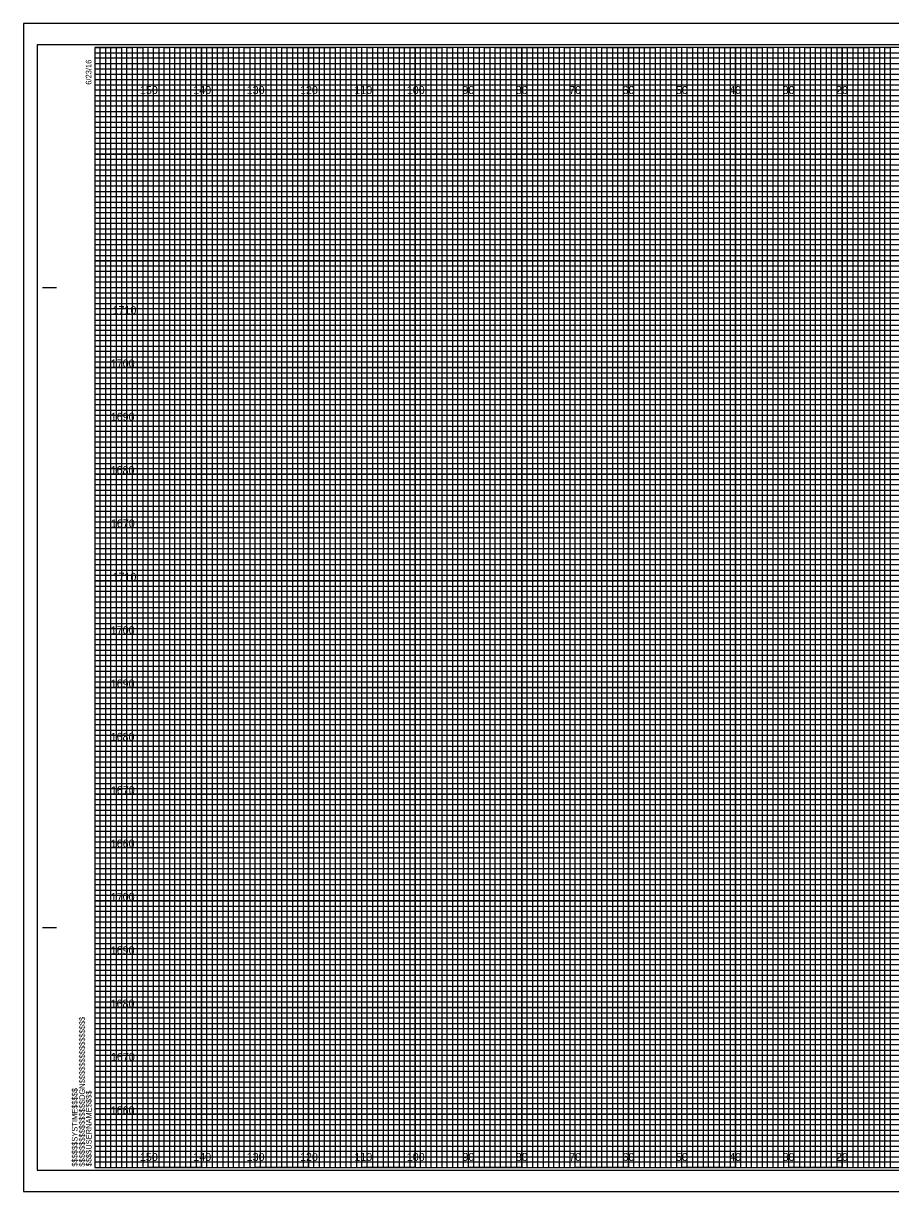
# Model space of a CAD drawing. Extents: x -13 to 323, y -5 to 2414.
# Drawn here: x -13.4 to 149.1, y 1975.5 to 2194.5 of the extents above; entities that cross this region are included whole.
import ezdxf

# ---------------------------------------------------------------- set-up
doc = ezdxf.new("R2010")
doc.units = 0
for name, color, linetype in [('Prop XS Elevation Labels', 7, 'Continuous'), ('Prop XS Offset Labels', 7, 'Continuous'), ('Sheet Cross Section CELL', 7, 'Continuous'), ('Sheet Cross Section Grid Major CELL', 7, 'Continuous'), ('Sheet Cross Section Grid Middle CELL', 7, 'Continuous'), ('Sheet Cross Section Grid Minor 1 CELL', 7, 'Continuous'), ('Sheet Cross Section Grid Minor 2 CELL', 7, 'Continuous'), ('Sheet Cutting Line CELL', 7, 'Continuous'), ('Sheet DOT Grid CELL', 7, 'Continuous'), ('Sheet Plot Border Inside CELL', 7, 'Continuous'), ('Sheet Plot Border Outside CELL', 7, 'Continuous')]:
    doc.layers.add(name, color=color, linetype=linetype)

msp = doc.modelspace()

# ---------------------------------------------------------------- linework, layer by layer
at = {"layer": 'Sheet Cross Section CELL'}
for p, q in [((-9.8, 2145), (-7.3, 2145)), ((-9.7, 2145), (-7.2, 2145)), ((-9.8, 2025), (-7.3, 2025)), ((-9.7, 2025), (-7.2, 2025)), ((0, 1980), (0, 1980)), ((0, 1980), (0, 1980)), ((0, 1980), (0, 1980)), ((0, 1980), (0, 1980)), ((0, 1980), (0, 1980)), ((0, 1980), (0, 1980)), ((0, 1980), (0, 1980))]:
    msp.add_line(p, q, dxfattribs=at)
msp.add_lwpolyline([(320, 2190), (0, 2190), (0, 1980), (320, 1980)], close=True, dxfattribs=at)
at = {"layer": 'Sheet Cross Section Grid Major CELL'}
for p, q in [((10, 2190), (0, 2190)), ((10, 1980), (10, 2190)), ((30, 2190), (20, 2190)), ((20, 2190), (20, 1980)), ((30, 1980), (30, 2190)), ((50, 2190), (40, 2190)), ((40, 2190), (40, 1980)), ((50, 1980), (50, 2190)), ((70, 2190), (60, 2190)), ((60, 2190), (60, 1980)), ((70, 1980), (70, 2190)), ((90, 2190), (80, 2190)), ((80, 2190), (80, 1980)), ((90, 1980), (90, 2190)), ((110, 2190), (100, 2190)), ((100, 2190), (100, 1980)), ((110, 1980), (110, 2190)), ((130, 2190), (120, 2190)), ((120, 2190), (120, 1980)), ((130, 1980), (130, 2190)), ((150, 2190), (140, 2190)), ((140, 2190), (140, 1980)), ((20, 1980), (10, 1980)), ((40, 1980), (30, 1980)), ((60, 1980), (50, 1980)), ((80, 1980), (70, 1980)), ((100, 1980), (90, 1980)), ((120, 1980), (110, 1980)), ((140, 1980), (130, 1980))]:
    msp.add_line(p, q, dxfattribs=at)
for points in [[(0, 2180), (320, 2180), (320, 2170), (0, 2170)], [(0, 2160), (320, 2160), (320, 2150), (0, 2150)], [(0, 2140), (320, 2140), (320, 2130), (0, 2130)], [(0, 2120), (320, 2120), (320, 2110), (0, 2110)], [(0, 2100), (320, 2100), (320, 2090), (0, 2090)], [(0, 2080), (320, 2080), (320, 2070), (0, 2070)], [(0, 2060), (320, 2060), (320, 2050), (0, 2050)], [(0, 2040), (320, 2040), (320, 2030), (0, 2030)], [(0, 2020), (320, 2020), (320, 2010), (0, 2010)], [(0, 2000), (320, 2000), (320, 1990), (0, 1990)]]:
    msp.add_lwpolyline(points, dxfattribs=at)
at = {"layer": 'Sheet Cross Section Grid Middle CELL'}
for points in [[(0, 2190), (5, 2190), (5, 1980), (15, 1980), (15, 2190), (25, 2190), (25, 1980), (35, 1980), (35, 2190), (45, 2190), (45, 1980), (55, 1980), (55, 2190), (65, 2190), (65, 1980), (75, 1980), (75, 2190), (85, 2190), (85, 1980), (95, 1980), (95, 2190), (105, 2190), (105, 1980), (115, 1980), (115, 2190), (125, 2190), (125, 1980), (135, 1980), (135, 2190), (145, 2190), (145, 1980), (155, 1980)], [(0, 2185), (275, 2185)], [(0, 2165), (320, 2165), (320, 2175), (0, 2175)], [(0, 2145), (320, 2145), (320, 2155), (0, 2155)], [(0, 2125), (320, 2125), (320, 2135), (0, 2135)], [(0, 2105), (320, 2105), (320, 2115), (0, 2115)], [(0, 2085), (320, 2085), (320, 2095), (0, 2095)], [(0, 2065), (320, 2065), (320, 2075), (0, 2075)], [(0, 2045), (320, 2045), (320, 2055), (0, 2055)], [(0, 2025), (320, 2025), (320, 2035), (0, 2035)], [(0, 2005), (320, 2005), (320, 2015), (0, 2015)], [(0, 1985), (320, 1985), (320, 1995), (0, 1995)]]:
    msp.add_lwpolyline(points, dxfattribs=at)
at = {"layer": 'Sheet Cross Section Grid Minor 1 CELL'}
for p, q in [((0, 2189), (260, 2189)), ((260, 2187.98), (0, 2187.98)), ((0, 2187.98), (0, 2187)), ((0, 2187), (260, 2187)), ((260, 2185.89), (0, 2185.89)), ((0, 2185.89), (0, 2184)), ((0, 2184), (320, 2184))]:
    msp.add_line(p, q, dxfattribs=at)
for points in [[(0, 2183), (270, 2183), (320, 2183), (320, 2182), (0, 2182)], [(0, 2181), (320, 2181), (320, 2179), (0, 2179)], [(0, 2178), (320, 2178), (320, 2177), (0, 2176.98)], [(0, 2176), (320, 2176), (320, 2174), (0, 2174)], [(0, 2173), (320, 2173), (320, 2172), (0, 2172)], [(0, 2171), (320, 2171), (320, 2169), (0, 2169)], [(0, 2168), (320, 2168), (320, 2167), (0, 2167)], [(0, 2166), (320, 2166), (320, 2164), (0, 2164)], [(0, 2163), (320, 2163), (320, 2162), (0, 2162)], [(0, 2161), (320, 2161), (320, 2159), (0, 2159)], [(0, 2158), (320, 2158), (320, 2157), (0, 2157)], [(0, 2156), (320, 2156), (320, 2153.95), (320, 2153), (320, 2152), (0, 2152)], [(0, 2154), (320, 2154), (320, 2153), (0, 2153)], [(0, 2151), (320, 2151), (320, 2149), (0, 2149.03)], [(0, 2149.03), (320, 2149), (320, 2148), (0, 2148)], [(0, 2147), (320, 2147), (320, 2146), (0, 2146)], [(0, 2144), (320, 2144), (320, 2143), (0, 2143)], [(0, 2142), (320, 2142), (320, 2141), (0, 2141)], [(-0.07, 2138.89), (320, 2138.89), (320, 2137.88), (-0.07, 2137.88)], [(0, 2137), (320, 2137), (320, 2136), (0, 2136)], [(0, 2134), (320, 2134), (320, 2133), (0, 2133)], [(0, 2132), (320, 2132), (320, 2131), (0, 2131)], [(0, 2129), (320, 2129), (320, 2128), (0, 2128)], [(0, 2127), (320, 2127), (320, 2126), (0, 2126)], [(0, 2124), (320, 2124), (320, 2123), (0, 2123)], [(0, 2122), (320, 2122), (320, 2121), (0, 2121)], [(0, 2119), (320, 2119), (319.99, 2117.98), (0, 2118)], [(0, 2117), (320, 2117), (320, 2116), (0, 2116)], [(0, 2114), (320, 2114), (320, 2113), (0, 2113)], [(0, 2112), (320, 2112), (320, 2111), (0, 2111)], [(0, 2109), (320, 2109), (320, 2108), (0, 2108)], [(0, 2107), (320, 2107), (320, 2106), (0, 2106)], [(0, 2104), (320, 2104), (320, 2103), (0, 2103)], [(0, 2102), (320, 2102), (320, 2101), (0, 2101)], [(0, 2099), (320, 2099), (320, 2098), (0, 2098)], [(0, 2096.99), (320.07, 2096.91), (320, 2096), (0, 2096)], [(0, 2094), (320, 2094), (320, 2093), (0, 2093)], [(0, 2092), (320, 2092), (320, 2091), (0, 2091)], [(0, 2089), (320, 2089), (320, 2088), (0, 2088)], [(0, 2087), (320, 2087), (320, 2086), (0, 2086)], [(0, 2084), (320, 2084), (320, 2083), (0, 2083)], [(0, 2082), (320, 2082), (320, 2081), (0, 2081)], [(0, 2079), (320, 2079), (320, 2078), (0, 2078)], [(0, 2077), (320, 2077), (320, 2076), (0, 2076)], [(0, 2074), (320, 2074), (320, 2073), (0, 2073)], [(0, 2072), (320, 2072), (320, 2071), (0, 2071)], [(0, 2069), (320, 2069), (320, 2068), (0, 2068)], [(0, 2067), (320, 2067), (320, 2066), (0, 2066)], [(0, 2064), (320, 2064), (320, 2063), (0, 2063)], [(0, 2062), (320, 2062), (320, 2061), (0, 2061)], [(0, 2059), (320, 2059), (319.99, 2057.98), (0, 2058)], [(0, 2057), (320, 2057), (320, 2056), (0, 2056)], [(0, 2054), (320, 2054), (320, 2053), (0, 2053)], [(0, 2052), (320, 2052), (320, 2051), (0, 2051)], [(0, 2049), (320, 2049), (320, 2048), (0, 2048)], [(0, 2047), (320, 2047), (320, 2046), (0, 2046)], [(0, 2044), (320, 2044), (320, 2043), (0, 2043)], [(0, 2042), (320, 2042), (320, 2041), (0, 2041)], [(0, 2039), (320, 2039), (320, 2038), (0, 2038)], [(0, 2036.99), (320.07, 2036.91), (320, 2036), (0, 2036)], [(0, 2034), (320, 2034), (320, 2033), (0, 2033)], [(0, 2032), (320, 2032), (320, 2031), (0, 2031)], [(0, 2029), (320, 2029), (320, 2028), (0, 2028)], [(0, 2027), (320, 2027), (320, 2026), (0, 2026)], [(0, 2024), (320, 2024), (320, 2023), (0, 2023)], [(0, 2022), (320, 2022), (320, 2021), (0, 2021)], [(0, 2019), (320, 2019), (320, 2018), (0, 2018)], [(0, 2017), (320, 2017), (320, 2016), (0, 2016)], [(0, 2014), (320, 2014), (320, 2013), (0, 2013)], [(0, 2012), (320, 2012), (320, 2011), (0, 2011)], [(0, 2009), (320, 2009), (320, 2008), (0, 2008)], [(0, 2007), (320, 2007), (320, 2006), (0, 2006)], [(0, 2004), (320, 2004), (320, 2003), (0, 2003)], [(0, 2002), (320, 2002), (320, 2001), (0, 2001)], [(0, 1999), (320, 1999), (320, 1998), (0, 1998)], [(0, 1997), (320, 1997), (320, 1996), (0, 1996)], [(0, 1994), (320, 1994), (320, 1993), (0, 1993)], [(0, 1992), (320, 1992), (320, 1991), (0, 1991)], [(0, 1989), (320, 1989), (320, 1988), (0, 1988)], [(0, 1987), (320, 1987), (320, 1986), (0, 1986)], [(0, 1984), (320, 1984), (320, 1983), (0, 1983)], [(0, 1982), (320, 1982), (320, 1981), (0, 1981)]]:
    msp.add_lwpolyline(points, dxfattribs=at)
at = {"layer": 'Sheet Cross Section Grid Minor 2 CELL'}
for points in [[(0, 1980), (1, 1980), (1, 2190), (2, 2190), (2, 1980)], [(2, 1980), (3, 1980), (3, 2190), (4, 2190), (4, 1980)], [(5, 1980), (6, 1980), (6, 2190), (7, 2190), (7, 1980)], [(7, 1980), (8, 1980), (8, 2190), (9, 2190), (9, 1980)], [(10, 1980), (11, 1980), (11, 2190), (12, 2190), (12, 1980)], [(12, 1980), (13, 1980), (13, 2190), (14, 2190), (14, 1980)], [(15, 1980), (16, 1980), (16, 2190), (17, 2190), (17, 1980)], [(17, 1980), (18, 1980), (18, 2190), (19, 2190), (19, 1980)], [(20, 1980), (21, 1980), (21, 2190), (22, 2190), (22, 1980)], [(22, 1980), (23, 1980), (23, 2190), (24, 2190), (24, 1980)], [(25, 1980), (26, 1980), (26, 2190), (27, 2190), (27, 1980)], [(27, 1980), (28, 1980), (28, 2190), (29, 2190), (29, 1980)], [(30, 1980), (31, 1980), (31, 2190), (32, 2190), (32, 1980)], [(32, 1980), (33, 1980), (33, 2190), (34, 2190), (34, 1980)], [(35, 1980), (36, 1980), (36, 2190), (37, 2190), (37, 1980)], [(37, 1980), (38, 1980), (38, 2190), (39, 2190), (39, 1980)], [(40, 1980), (41, 1980), (41, 2190), (42, 2190), (42, 1980)], [(42, 1980), (43, 1980), (43, 2190), (44, 2190), (44, 1980)], [(45, 1980), (46, 1980), (46, 2190), (47, 2190), (47, 1980)], [(47, 1980), (48, 1980), (48, 2190), (49, 2190), (49, 1980)], [(50, 1980), (51, 1980), (51, 2190), (52, 2190), (52, 1980)], [(52, 1980), (53, 1980), (53, 2190), (54, 2190), (54, 1980)], [(55, 1980), (56, 1980), (56, 2190), (57, 2190), (57, 1980)], [(57, 1980), (58, 1980), (58, 2190), (59, 2190), (59, 1980)], [(60, 1980), (61, 1980), (61, 2190), (62, 2190), (62, 1980)], [(62, 1980), (63, 1980), (63, 2190), (64, 2190), (64, 1980)], [(65, 1980), (66, 1980), (66, 2190), (67, 2190), (67, 1980)], [(67, 1980), (68, 1980), (68, 2190), (69, 2190), (69, 1980)], [(70, 1980), (71, 1980), (71, 2190), (72, 2190), (72, 1980)], [(72, 1980), (73, 1980), (73, 2190), (74, 2190), (74, 1980)], [(75, 1980), (76, 1980), (76, 2190), (77, 2190), (77, 1980)], [(77, 1980), (78, 1980), (78, 2190), (79, 2190), (79, 1980)], [(80, 1980), (81, 1980), (81, 2190), (82, 2190), (82, 1980)], [(82, 1980), (83, 1980), (83, 2190), (84, 2190), (84, 1980)], [(85, 1980), (86, 1980), (86, 2190), (87, 2190), (87, 1980)], [(87, 1980), (88, 1980), (88, 2190), (89, 2190), (89, 1980)], [(90, 1980), (91, 1980), (91, 2190), (92, 2190), (92, 1980)], [(92, 1980), (93, 1980), (93, 2190), (94, 2190), (94, 1980)], [(95, 1980), (96, 1980), (96, 2190), (97, 2190), (97, 1980)], [(97, 1980), (98, 1980), (98, 2190), (99, 2190), (99, 1980)], [(100, 1980), (101, 1980), (101, 2190), (102, 2190), (102, 1980)], [(102, 1980), (103, 1980), (103, 2190), (104, 2190), (104, 1980)], [(105, 1980), (106, 1980), (106, 2190), (107, 2190), (107, 1980)], [(107, 1980), (108, 1980), (108, 2190), (109, 2190), (109, 1980)], [(110, 1980), (111, 1980), (111, 2190), (112, 2190), (112, 1980)], [(112, 1980), (113, 1980), (113, 2190), (114, 2190), (114, 1980)], [(115, 1980), (116, 1980), (116, 2190), (117, 2190), (117, 1980)], [(117, 1980), (118, 1980), (118, 2190), (119, 2190), (119, 1980)], [(120, 1980), (121, 1980), (121, 2190), (122, 2190), (122, 1980)], [(122, 1980), (123, 1980), (123, 2190), (124, 2190), (124, 1980)], [(125, 1980), (126, 1980), (126, 2190), (127, 2190), (127, 1980)], [(127, 1980), (128, 1980), (128, 2190), (129, 2190), (129, 1980)], [(130, 1980), (131, 1980), (131, 2190), (132, 2190), (132, 1980)], [(132, 1980), (133, 1980), (133, 2190), (134, 2190), (134, 1980)], [(135, 1980), (136, 1980), (136, 2190), (137, 2190), (137, 1980)], [(137, 1980), (138, 1980), (138, 2190), (139, 2190), (139, 1980)], [(140, 1980), (141, 1980), (141, 2190), (142, 2190), (142, 1980)], [(142, 1980), (143, 1980), (143, 2190), (144, 2190), (144, 1980)], [(145, 1980), (146, 1980), (146, 2190), (147, 2190), (147, 1980)], [(147, 1980), (148, 1980), (148, 2190), (149, 2190), (149, 1980)]]:
    msp.add_lwpolyline(points, dxfattribs=at)
at = {"layer": 'Sheet Cutting Line CELL'}
for p, q in [((323.3, 2194.5), (-13.4, 2194.5)), ((-13.4, 2194.5), (-13.4, 1975.5)), ((-13.4, 1975.5), (323.3, 1975.5))]:
    msp.add_line(p, q, dxfattribs=at)
at = {"layer": 'Sheet DOT Grid CELL'}
for p, q in [((10, 1980), (10, 2190)), ((20, 1980), (20, 2190)), ((30, 1980), (30, 2190)), ((40, 1980), (40, 2190)), ((50, 1980), (50, 2190)), ((60, 1980), (60, 2190)), ((70, 1980), (70, 2190)), ((80, 1980), (80, 2190)), ((90, 1980), (90, 2190)), ((100, 1980), (100, 2190)), ((110, 1980), (110, 2190)), ((120, 1980), (120, 2190)), ((130, 1980), (130, 2190)), ((140, 1980), (140, 2190)), ((0, 2180), (320, 2180)), ((0, 2170), (320, 2170)), ((0, 2160), (320, 2160)), ((0, 2150), (320, 2150)), ((0, 2140), (320, 2140)), ((0, 2130), (320, 2130)), ((0, 2120), (320, 2120)), ((0, 2110), (320, 2110)), ((0, 2100), (320, 2100)), ((0, 2090), (320, 2090)), ((0, 2080), (320, 2080)), ((0, 2070), (320, 2070)), ((0, 2060), (320, 2060)), ((0, 2050), (320, 2050)), ((0, 2040), (320, 2040)), ((0, 2030), (320, 2030)), ((0, 2020), (320, 2020)), ((0, 2010), (320, 2010)), ((0, 2000), (320, 2000)), ((0, 1990), (320, 1990))]:
    msp.add_line(p, q, dxfattribs=at)
at = {"layer": 'Sheet Plot Border Inside CELL'}
msp.add_lwpolyline([(-10.8, 1979.5), (322.4, 1979.5), (322.4, 2190.5), (-10.8, 2190.5)], close=True, dxfattribs=at)
at = {"layer": 'Sheet Plot Border Outside CELL'}
msp.add_lwpolyline([(-13.4, 1975.5), (323.3, 1975.5), (323.3, 2194.5), (-13.4, 2194.5)], close=True, dxfattribs=at)

# ---------------------------------------------------------------- texts
at = {"layer": 'Prop XS Elevation Labels'}
for s, p in [('1710', (3.31, 2140)), ('1700', (2.98, 2130)), ('1690', (2.97, 2120)), ('1680', (2.95, 2110)), ('1670', (3, 2100)), ('1710', (3.31, 2090)), ('1700', (2.98, 2080)), ('1690', (2.97, 2070)), ('1680', (2.95, 2060)), ('1670', (3, 2050)), ('1660', (2.97, 2040)), ('1700', (2.98, 2030)), ('1690', (2.97, 2020)), ('1680', (2.95, 2010)), ('1670', (3, 2000)), ('1660', (2.97, 1990))]:
    msp.add_text(s, height=1.5, dxfattribs=at).set_placement(p)
at = {"layer": 'Prop XS Offset Labels'}
for s, p in [('150', (8.44, 2181.25)), ('140', (18.44, 2181.25)), ('130', (28.44, 2181.25)), ('120', (38.44, 2181.25)), ('110', (48.62, 2181.25)), ('100', (58.44, 2181.25)), ('90', (68.86, 2181.25)), ('80', (78.86, 2181.25)), ('70', (88.86, 2181.25)), ('60', (98.86, 2181.25)), ('50', (108.86, 2181.25)), ('40', (118.86, 2181.25)), ('30', (128.86, 2181.25)), ('20', (138.86, 2181.25)), ('150', (8.44, 1981.25)), ('140', (18.44, 1981.25)), ('130', (28.44, 1981.25)), ('120', (38.44, 1981.25)), ('110', (48.62, 1981.25)), ('100', (58.44, 1981.25)), ('90', (68.86, 1981.25)), ('80', (78.86, 1981.25)), ('70', (88.86, 1981.25)), ('60', (98.86, 1981.25)), ('50', (108.86, 1981.25)), ('40', (118.86, 1981.25)), ('30', (128.86, 1981.25)), ('20', (138.86, 1981.25))]:
    msp.add_text(s, height=1.5, dxfattribs=at).set_placement(p)
at = {"layer": 'Sheet Cross Section CELL'}
for s, p in [('6/23/16', (-0.65, 2183)), ('$$$$$$$$$$$$$$$$DGN$$$$$$$$$$$$$$$$', (-1.88, 1980.18)), ('$$$$$$SYSTIME$$$$$', (-3.26, 1980.18)), ('$$$$USERNAME$$$$', (-0.62, 1980.23))]:
    msp.add_text(s, height=1.05, rotation=90, dxfattribs=at).set_placement(p)

doc.saveas('drawing.dxf')
